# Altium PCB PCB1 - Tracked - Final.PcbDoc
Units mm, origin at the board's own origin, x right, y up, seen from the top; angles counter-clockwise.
Board outline 152.4 x 101.6 mm, 4 copper layers (Top Layer, Internal Plane 1, Internal Plane 2, Bottom Layer), stack 0.462 mm thick; 14 components, 52 nets, 174 pads, 10 vias.
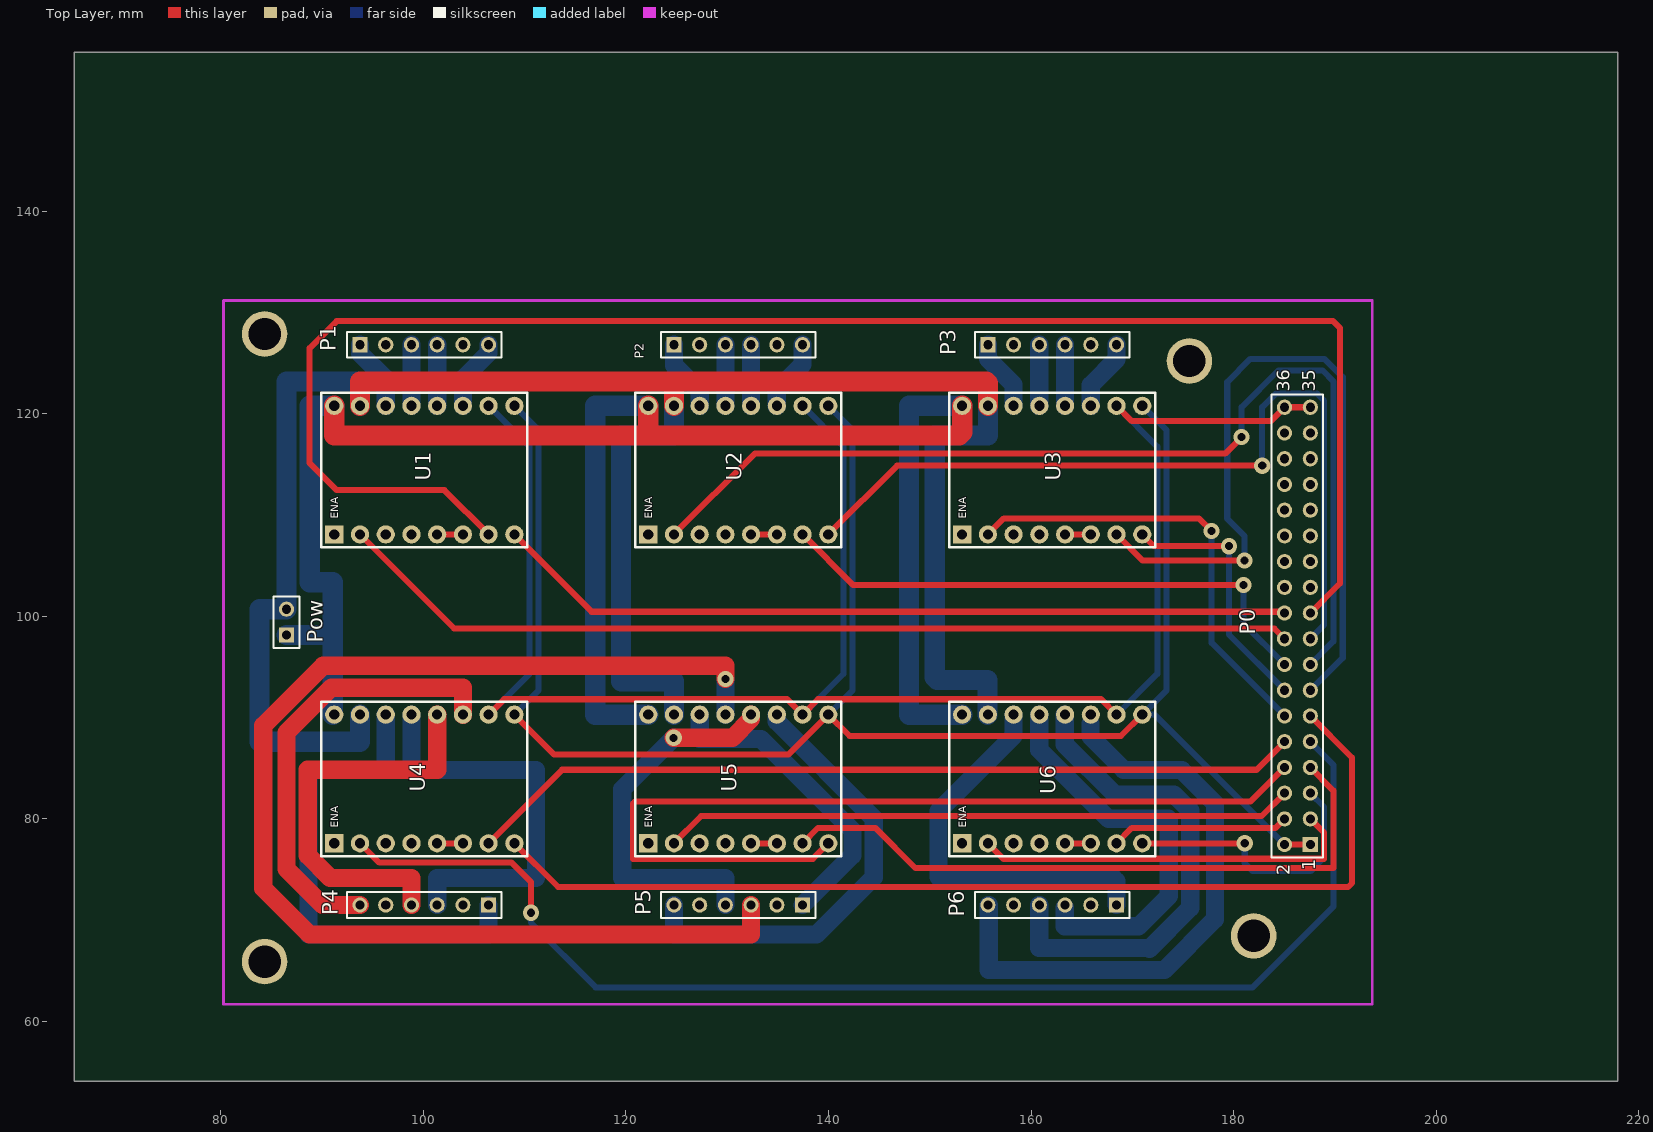
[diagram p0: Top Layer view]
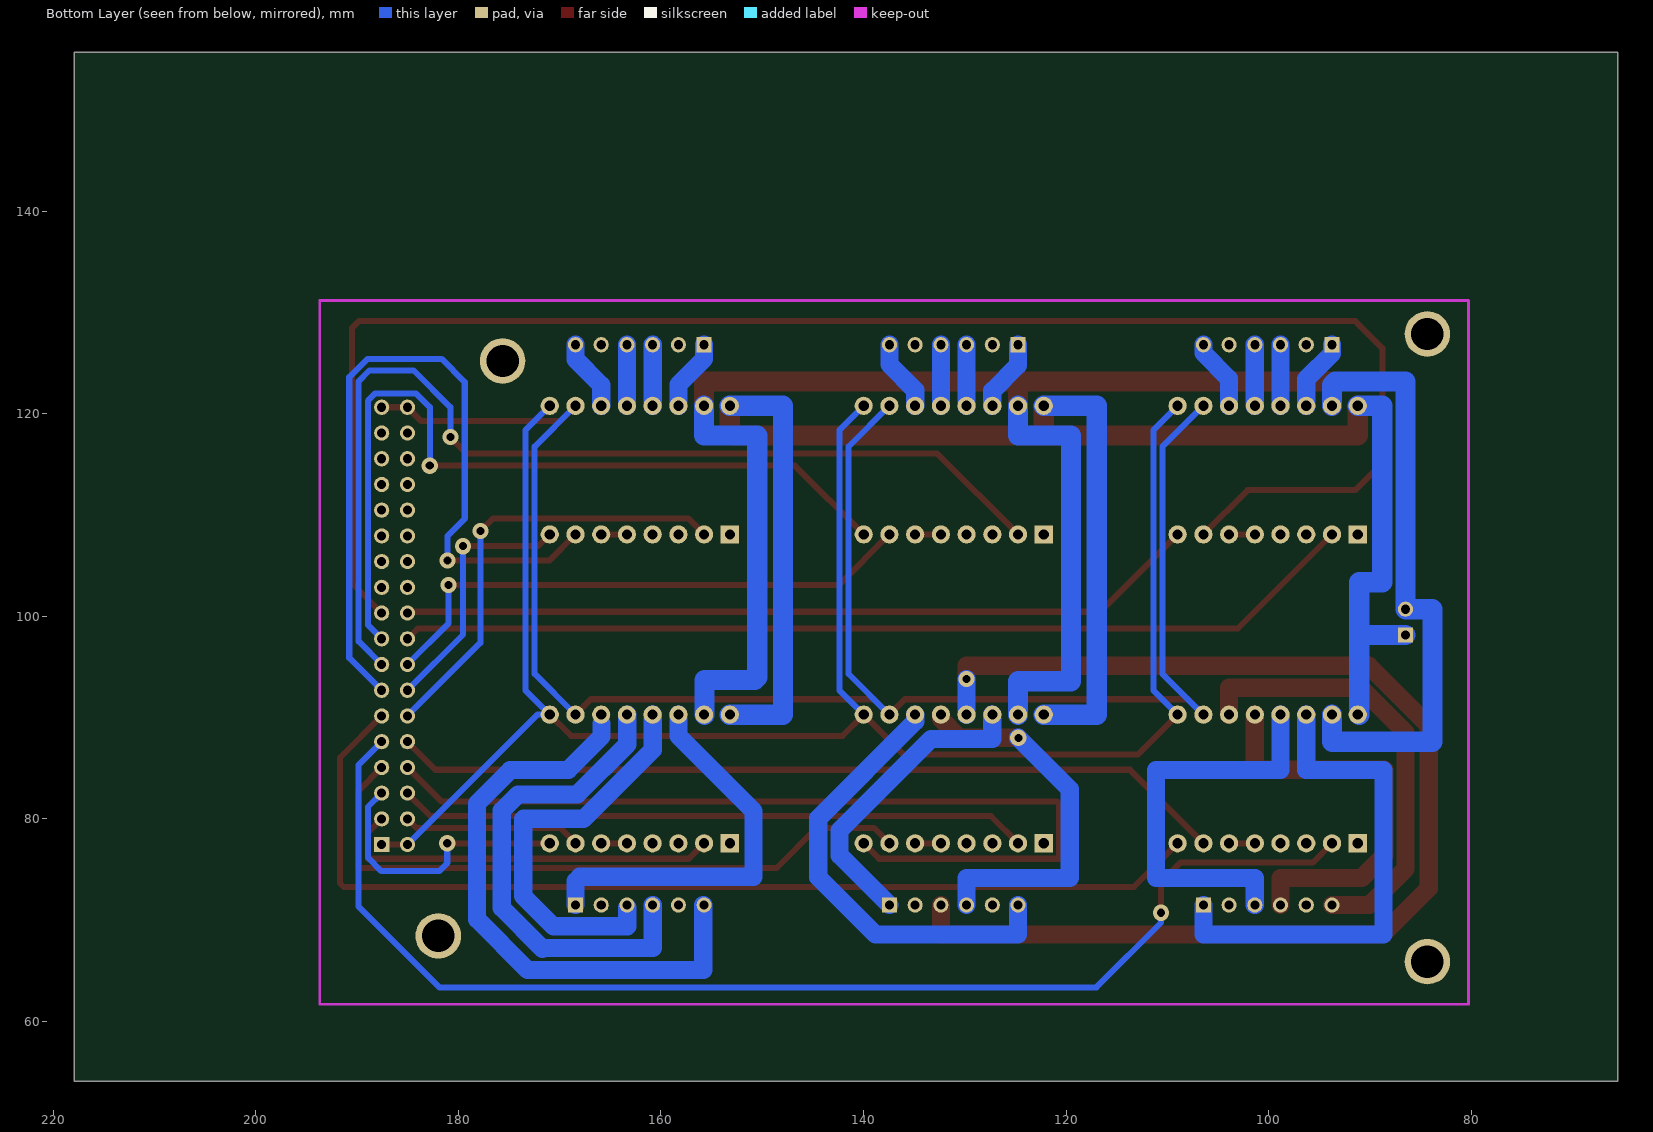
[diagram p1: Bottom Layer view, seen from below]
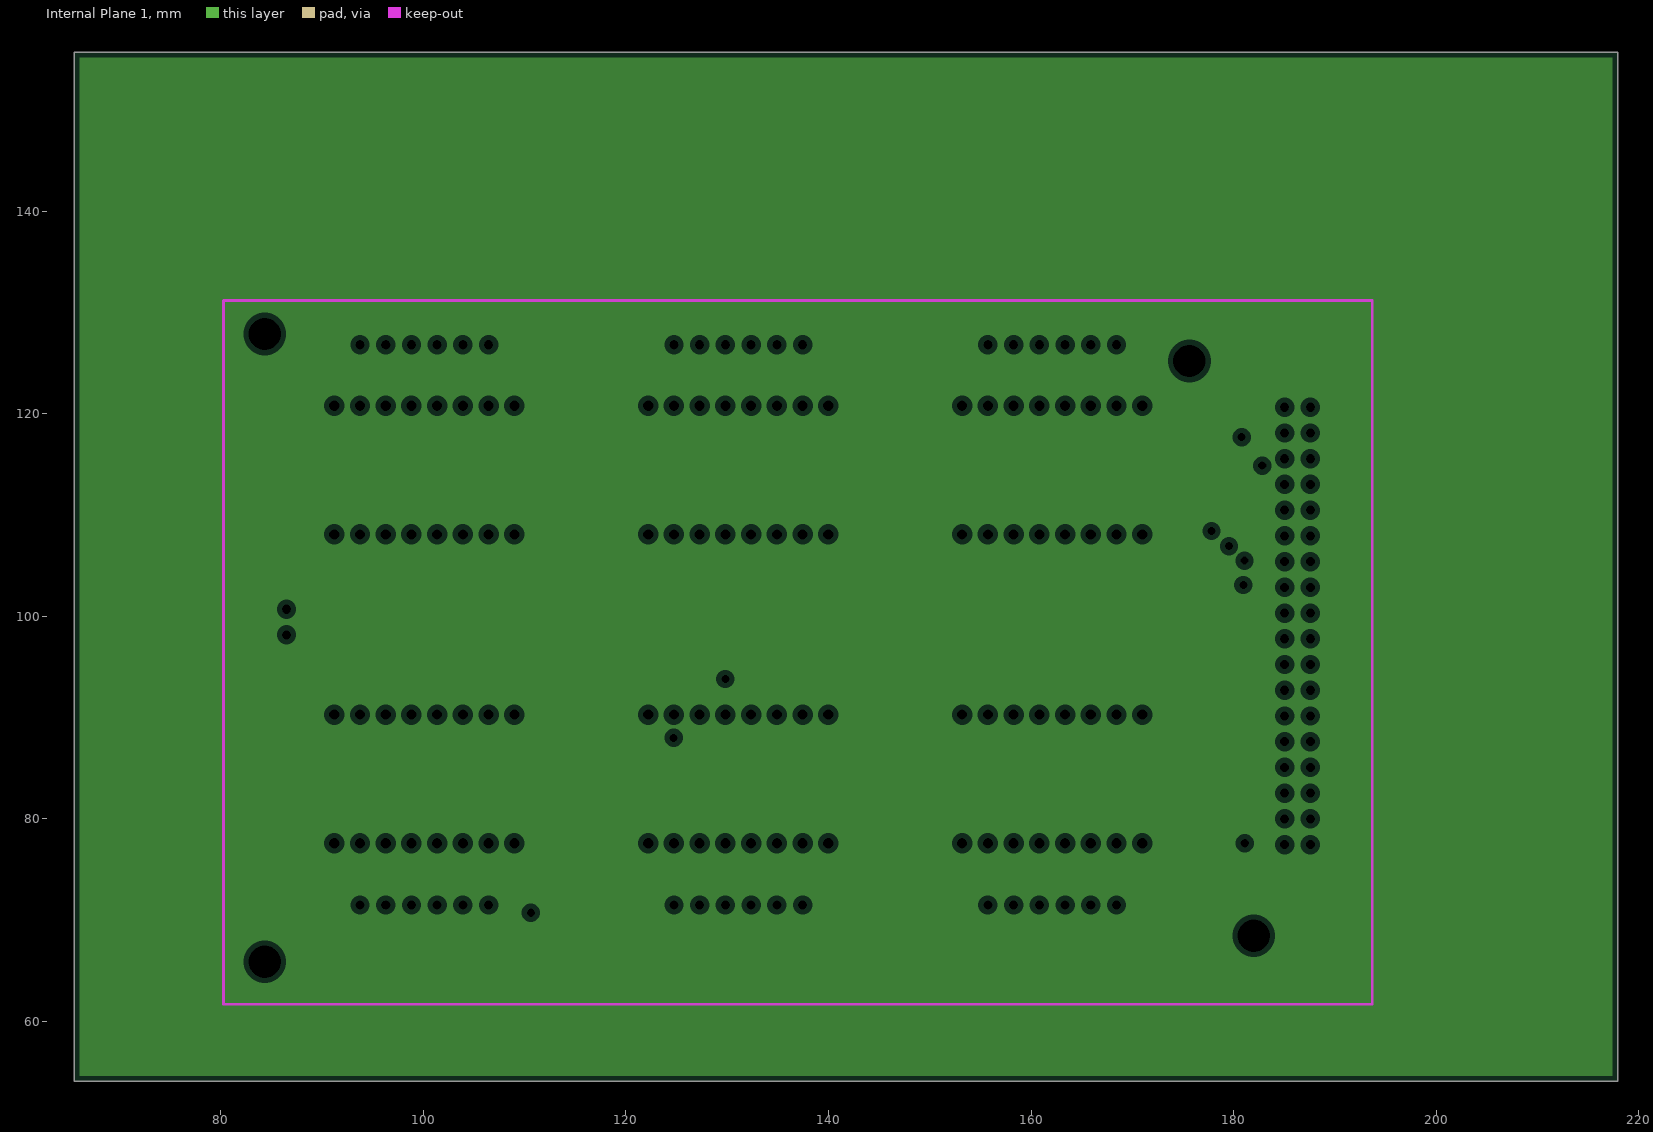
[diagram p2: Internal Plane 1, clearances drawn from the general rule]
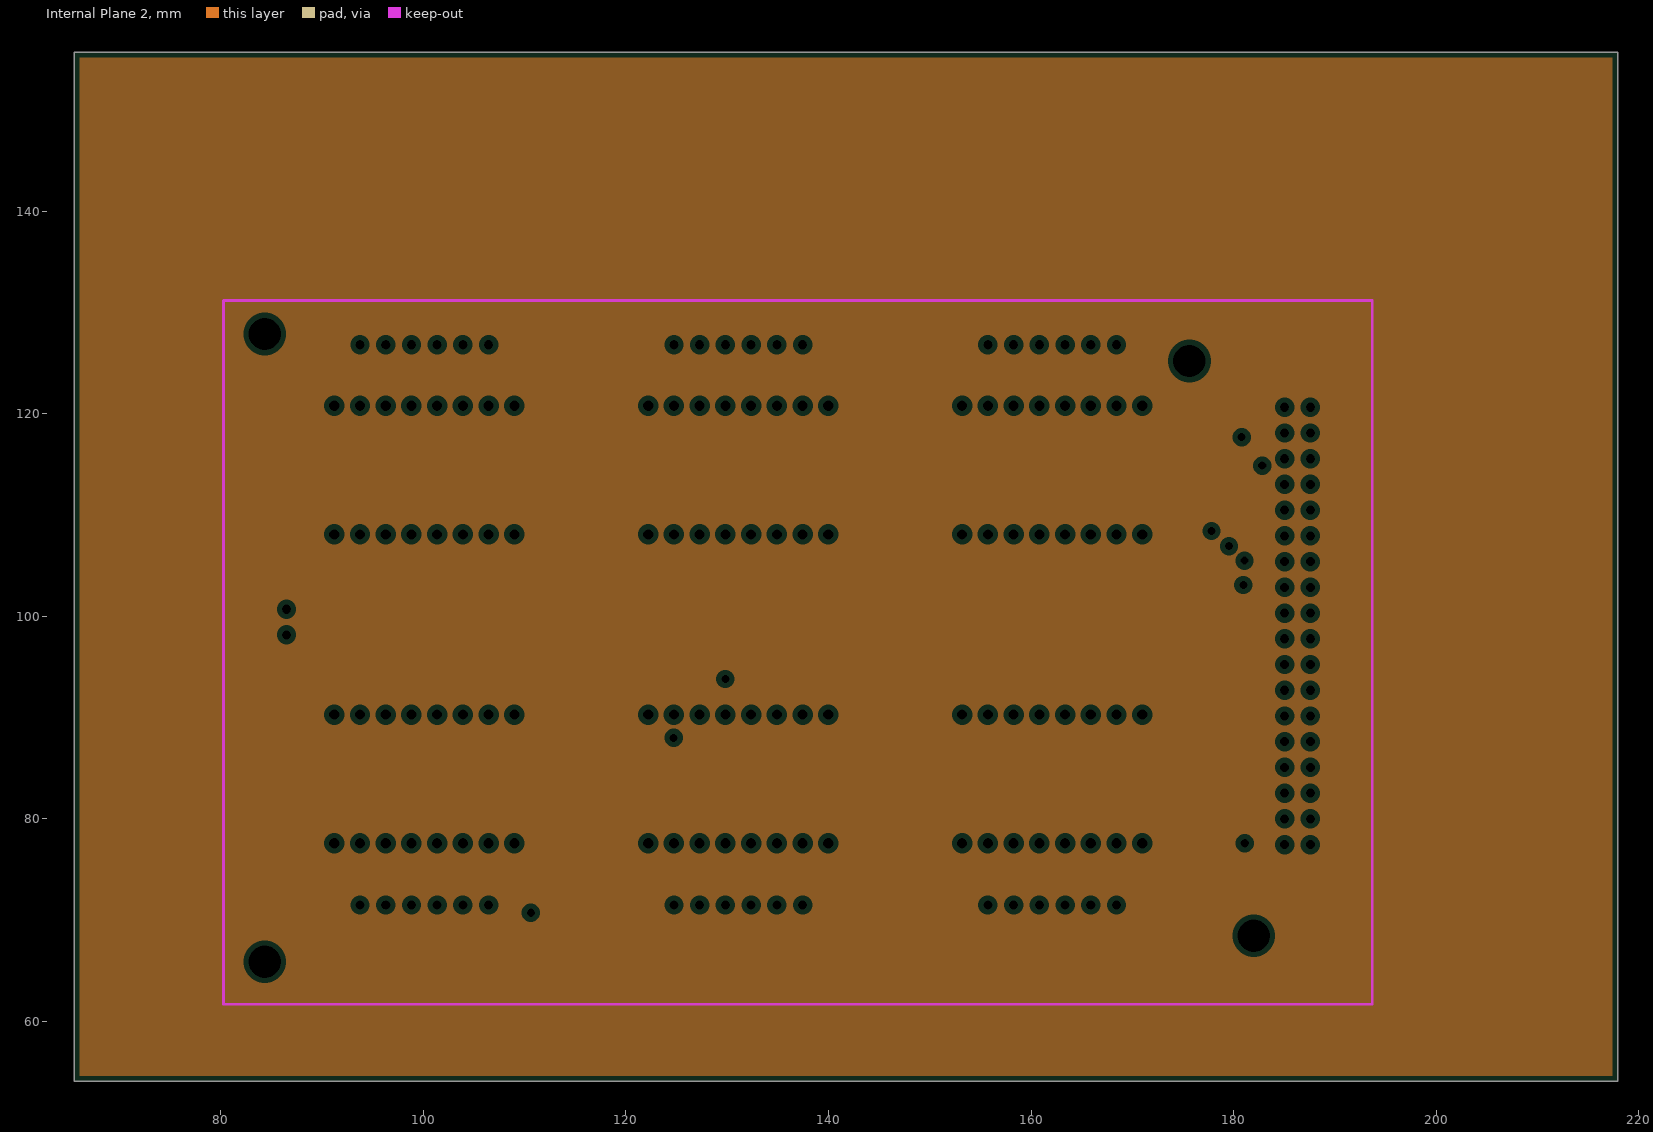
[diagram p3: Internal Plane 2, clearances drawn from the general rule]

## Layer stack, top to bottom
Top Solder: solder mask 0.0102, Solder Resist, Dk 3.5
Top Layer: signal copper 0.0356
Internal Plane 1: plane copper 0.0356
Internal Plane 2: plane copper 0.0356
Dielectric1: dielectric 0.32, FR-4, Dk 4.8
Bottom Layer: signal copper 0.0356
Bottom Solder: solder mask 0.0102, Solder Resist, Dk 3.5

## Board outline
65.532,54.102 65.532,155.702 217.932,155.702 217.932,54.102

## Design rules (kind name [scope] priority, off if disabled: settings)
AssemblyTestPointUsage AssemblyTestPointUsage_1 [All] p2:
AssemblyTestpoint AssemblyTestpoint_1 [All] p2: testpointundercomponent=TRUE minsize=1.016 maxsize=2.54 preferedsize=1.524 minholesize=0 maxholesize=1.016 preferedholesize=0.813 testpointgrid=0.025 usegrid=TRUE gridtolerance=0 allowsidetop=TRUE allowsidebottom=TRUE
Clearance [All] p1: gap=0.3
ComponentClearance ComponentClearance_1 [All] p2: gap=0.254 collisioncheckmode=3 verticalgap=0.254 showdistances=FALSE
DiffPairsRouting DiffPairsRouting_1 [All] p2: maxlimit=0.254 minlimit=0.254 mostfreqgap=0.254 toplayer_minwidth=0.381 toplayer_maxwidth=0.381 toplayer_prefwidth=0.381 bottomlayer_minwidth=0.381 bottomlayer_maxwidth=0.381 bottomlayer_prefwidth=0.381 maxuncoupledlength=12.7
FabricationTestPointUsage TestPointUsage [All] p2: valid=0 allowmultiple=FALSE
FabricationTestpoint Testpoint [All] p2: side=3 testpointundercomponent=TRUE minsize=1.016 maxsize=2.54 preferedsize=1.524 minholesize=0 maxholesize=1.016 preferedholesize=0.813 testpointgrid=0.025 allowsidetop=TRUE allowsidebottom=TRUE usegrid=TRUE gridtolerance=0
FanoutControl Fanout_LCC [IsLCC] p1: bgadir=Out bgaviamode=Centered fanoutstyle=Auto fanoutdirection=Alternating viagrid=0.025 // Fanout_LCC (Default Rule)
FanoutControl Fanout_BGA [IsBGA] p2: bgadir=Out bgaviamode=Centered fanoutstyle=Auto fanoutdirection=Alternating viagrid=0.025 // Fanout_BGA (Default Rule)
FanoutControl Fanout_Default [All] p4: bgadir=Out bgaviamode=Centered fanoutstyle=Auto fanoutdirection=Alternating viagrid=0.025 // Fanout_Default (Default Rule)
FanoutControl Fanout_Small [(CompPinCount < 5)] p5: bgadir=Out bgaviamode=Centered fanoutstyle=Auto fanoutdirection=OutThenIn viagrid=0.025 // Fanout_Small (Default Rule)
FanoutControl Fanout_BGA_1 [IsBGA] p6: bgadir=Out bgaviamode=Centered fanoutstyle=Auto fanoutdirection=Alternating viagrid=0.025 // Fanout_BGA (Default Rule)
FanoutControl Fanout_LCC_1 [IsLCC] p7: bgadir=Out bgaviamode=Centered fanoutstyle=Auto fanoutdirection=Alternating viagrid=0.025 // Fanout_LCC (Default Rule)
FanoutControl Fanout_SOIC_1 [IsSOIC] p8: bgadir=Out bgaviamode=Centered fanoutstyle=Auto fanoutdirection=Alternating viagrid=0.025 // Fanout_SOIC (Default Rule)
FanoutControl Fanout_Small_1 [(CompPinCount < 5)] p9: bgadir=Out bgaviamode=Centered fanoutstyle=Auto fanoutdirection=OutThenIn viagrid=0.025 // Fanout_Small (Default Rule)
FanoutControl Fanout_Default_1 [All] p10: bgadir=Out bgaviamode=Centered fanoutstyle=Auto fanoutdirection=Alternating viagrid=0.025 // Fanout_Default (Default Rule)
Height Height_1 [All] p2: minheight=0 maxheight=25.4 prefheight=12.7
HoleSize HoleSize_1 [All] p2: absolutevalues=TRUE maxlimit=2.54 minlimit=0.025 maxpercent=80.000 minpercent=20.000
HoleToHoleClearance HoleToHoleClearance_1 [All] p2: gap=0.254 allowstackedmicrovias=TRUE
LayerPairs LayerPairs_1 [All] p2: enforce=TRUE
MinimumSolderMaskSliver MinimumSolderMaskSliver_1 [All] p2: minsoldermaskwidth=0.254
NetAntennae NetAntennae_1 [All] p2: netantennaetolerance=0
PasteMaskExpansion PasteMaskExpansion_1 [All] p2: expansion=0
PlaneClearance [All] p1: clearance=0.508
PlaneClearance PlaneClearance_1 [All] p2: clearance=0.508
PlaneConnect [All] p1: planeconnectstyle=Relief reliefexpansion=0.508 reliefentries=4 reliefconductorwidth=0.254 reliefairgap=0.254
PolygonConnect [All] p1: connectstyle=Relief reliefconductorwidth=0.254 reliefentries=4 polygonreliefangle="90 Angle" airgapwidth=0.254
PolygonConnect PolygonConnect_1 [All] p2: connectstyle=Relief reliefconductorwidth=0.254 reliefentries=4 polygonreliefangle="90 Angle" airgapwidth=0.254
RoutingPriority RoutingPriority_1 [All] p2: routingpriority=0
RoutingTopology RoutingTopology_1 [All] p2: topology=Shortest
RoutingVias [All] p1: holewidth=0.8 width=1.6 viastyle="Through Hole" minholewidth=0.711 minwidth=1.27 maxholewidth=0.711 maxwidth=1.27
ShortCircuit ShortCircuit_1 [All] p2: allowed=FALSE
SilkToBoardRegionClearance SilkToBoardRegionClearance_1 [All] p2:
SilkToSilkClearance SilkToSilkClearance_1 [All] p2: silktosilkclearance=0.254
SilkToSolderMaskClearance SilkscreenOverComponentPads [IsPad] p2: minsilkscreentomaskgap=0.254 clearancetoexposedcopper=TRUE
SolderMaskExpansion [All] p1: expansion=0.102
SolderMaskExpansion SolderMaskExpansion_1 [All] p2: expansion=0.102
UnRoutedNet UnRoutedNet_1 [All] p2:
UnpouredPolygon UnpouredPolygon_1 [All] p2:
Width [All] p1: maxlimit=1.8 minlimit=0.6 preferedwidth=0.6
24 further rules are at their usual default settings.

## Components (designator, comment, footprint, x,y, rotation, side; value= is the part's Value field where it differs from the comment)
P0 "Header 18X2" HDR2X18 187.579,77.47 r90 top
P1 "Header 6" HDR1X6#1 93.744,126.825 r0 top
P2 "Header 6" HDR1X6#1 124.744,126.825 r0 top
P3 "Header 6" HDR1X6#1 155.744,126.825 r0 top
P4 "Header 6" HDR1X6#2 93.744,71.501 r0 top
P5 "Header 6" HDR1X6#2 124.744,71.501 r0 top
P6 "Header 6" HDR1X6#2 155.744,71.501 r0 top
Pow "Header 2" HDR1X2 86.487,98.171 r90 top
U1 "Stepper motor driver" PCBDriver_1 110,106.825 r90 top
U2 "Stepper motor driver" PCBDriver_1 141,106.825 r90 top
U3 "Stepper motor driver" PCBDriver_1 172,106.825 r90 top
U4 "Stepper motor driver" PCBDriver_1 110,76.327 r90 top
U5 "Stepper motor driver" PCBDriver_1 141,76.327 r90 top
U6 "Stepper motor driver" PCBDriver_1 172,76.327 r90 top

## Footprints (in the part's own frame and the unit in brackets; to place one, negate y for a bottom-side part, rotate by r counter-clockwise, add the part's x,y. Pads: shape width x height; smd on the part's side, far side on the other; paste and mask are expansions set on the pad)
HDR1X2 [mm] "Connector; Header; 2 Position"
  rect 1.5x1.5 hole 0.9: 1(0,0)
  round 1.5 hole 0.9: 2(2.54,0)
  silkscreen extent -1.27,-1.27 3.81,1.27
HDR1X6#1 [mm] "Connector; Header; 6 Position"
  rect 1.5x1.5 hole 0.9: 1(0,0)
  round 1.5 hole 0.9: 2(2.54,0) 3(5.08,0) 4(7.62,0) 5(10.16,0) 6(12.7,0)
  silkscreen extent -1.27,-1.27 13.97,1.27
HDR1X6#2 [mm] "Connector; Header; 6 Position"
  round 1.5 hole 0.9: 1(0,0) 2(2.54,0) 3(5.08,0) 4(7.62,0) 5(10.16,0)
  rect 1.5x1.5 hole 0.9: 6(12.7,0)
  silkscreen extent -1.27,-1.27 13.97,1.27
HDR2X18 [mm] "Connector; Header; 18x2 Position"
  rect 1.5x1.5 hole 0.9: 1(0,0)
  round 1.5 hole 0.9: 2(0,2.54) 3(2.54,0) 4(2.54,2.54) 5(5.08,0) 6(5.08,2.54) 7(7.62,0) 8(7.62,2.54) 9(10.16,0) 10(10.16,2.54) 11(12.7,0) 12(12.7,2.54) 13(15.24,0) 14(15.24,2.54) 15(17.78,0) 16(17.78,2.54) 17(20.32,0) 18(20.32,2.54) 19(22.86,0) 20(22.86,2.54) 21(25.4,0) 22(25.4,2.54) 23(27.94,0) 24(27.94,2.54) 25(30.48,0) 26(30.48,2.54) 27(33.02,0) 28(33.02,2.54) 29(35.56,0) 30(35.56,2.54) 31(38.1,0) 32(38.1,2.54) 33(40.64,0) 34(40.64,2.54) 35(43.18,0) 36(43.18,2.54)
  silkscreen extent -1.27,-1.27 44.45,3.81
PCBDriver_1 [mm] "Stepper motor driver A4988"
  rect 1.8x1.8 hole 1: 0(1.27,18.796)
  round 1.8 hole 1: 1(1.27,16.256) 2(1.27,13.716) 3(1.27,11.176) 4(1.27,8.636) 5(1.27,6.096) 6(1.27,3.556) 7(1.27,1.016) 8(13.97,1.016) 9(13.97,3.556) 10(13.97,6.096) 11(13.97,8.636) 12(13.97,11.176) 13(13.97,13.716) 14(13.97,16.256) 15(13.97,18.796)
  silkscreen extent 0,-0.25 15.24,20.07

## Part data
P0: "Header, 18-Pin, Dual row"
P1 P2 P3 P4 P5 P6: "Header, 6-Pin"
Pow: "Header, 2-Pin"
U1 U2 U3 U4 U5 U6: library part Driver_1, "Stepper Motor Driver module A4988"

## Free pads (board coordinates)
  round 4.5 hole 3.2: 0(84.328,65.913) 0(84.328,127.889) 0(175.641,125.222) 0(181.991,68.453)

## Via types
v1: diameter 1.6, hole 0.8, Top Layer to Bottom Layer, 10 vias

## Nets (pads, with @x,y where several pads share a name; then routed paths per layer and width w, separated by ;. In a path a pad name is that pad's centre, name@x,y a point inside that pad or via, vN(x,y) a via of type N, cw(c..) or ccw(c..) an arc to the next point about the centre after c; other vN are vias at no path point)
NetP0_1: P0.1 P0.2 U1.8 U2.8 U3.8 U4.8 U5.8 U6.8 | length 186.4
  Top Layer w0.6: U4.8 112.921,86.36 136.047,86.36 U5.8 142.092,88.189 168.876,88.189 U6.8 ; P0.2 P0.1
  Bottom Layer w0.6: U4.8 111.384,92.697 111.384,118.395 U1.8 ; U5.8 142.384,92.697 142.384,118.395 U2.8 ; U3.8 173.384,118.395 173.384,92.697 U6.8 172.212,90.297 P0.2
NetP0_3: P0.3 U6.1 | length 38.3
  Top Layer w0.6: U6.1 157.268,76.073 188.951,76.073 188.951,78.638 P0.3
NetP0_4: P0.4 U6.6 | length 17.6
  Top Layer w0.6: U6.6 169.968,79.121 184.15,79.121 P0.4
NetP0_5: P0.5 U6.7 | length 27.7
  Top Layer w0.6: U6.7 v1(181.102,77.597)
  Bottom Layer w0.6: v1(181.102,77.597) 181.102,75.641 181.889,74.854 187.604,74.854 188.951,76.2 188.951,81.178 P0.5
NetP0_6: P0.6 U5.1 | length 62.3
  Top Layer w0.6: U5.1 127.436,80.289 182.778,80.289 P0.6
NetP0_7: P0.7 U5.6 | length 65.6
  Top Layer w0.6: U5.6 138.968,79.121 144.628,79.121 148.59,75.159 189.865,75.159 189.865,82.804 P0.7
NetP0_8: P0.8 U5.7 | length 91.2
  Top Layer w0.6: U5.7 138.46,76.073 120.701,76.073 120.701,81.509 120.929,81.737 181.686,81.737 P0.8
NetP0_9: P0.9 U4.1 | length 124.9
  Top Layer w0.6: U4.1 95.649,75.692 108.712,75.692 110.617,73.787 v1(110.617,70.739)
  Bottom Layer w0.6: v1(110.617,70.739) 110.617,69.774 117.018,63.373 181.889,63.373 189.865,71.349 189.865,85.344 P0.9
NetP0_10: P0.10 U4.6 | length 82.8
  Top Layer w0.6: U4.6 113.708,84.861 182.27,84.861 P0.10
NetP0_11: P0.11 U4.7 | length 102.9
  Top Layer w0.6: U4.7 113.302,73.279 191.313,73.279 191.694,73.66 191.694,86.055 P0.11
NetP0_12: P0.12 U3.1 | length 44.5
  Top Layer w0.6: U3.1 157.326,109.677 176.581,109.677 v1(177.825,108.433)
  Bottom Layer w0.6: v1(177.825,108.433) 177.825,97.384 P0.12
NetP0_13: P0.13 U3.6 | length 77.4
  Top Layer w0.6: U3.6 171.027,105.512 v1(181.077,105.512)
  Bottom Layer w0.6: v1(181.077,105.512) 181.077,107.95 179.375,109.652 179.375,123.141 181.659,125.425 188.976,125.425 190.779,123.622 190.779,95.91 P0.13
NetP0_14: P0.14 U3.7 | length 25.5
  Top Layer w0.6: U3.7 172.145,106.934 v1(179.553,106.934)
  Bottom Layer w0.6: v1(179.553,106.934) 179.553,98.196 P0.14
NetP0_15: P0.15 U2.1 | length 102.9
  Top Layer w0.6: U2.1 132.727,116.078 179.172,116.078 v1(180.797,117.704)
  Bottom Layer w0.6: v1(180.797,117.704) 180.797,120.65 184.429,124.282 188.798,124.282 189.865,123.215 189.865,97.536 P0.15
NetP0_16: P0.16 U2.6 | length 55.1
  Top Layer w0.6: U2.6 142.44,103.099 v1(180.975,103.099)
  Bottom Layer w0.6: v1(180.975,103.099) 180.975,99.314 P0.16
NetP0_17: P0.17 U2.7 | length 82.5
  Top Layer w0.6: U2.7 146.773,114.884 v1(182.829,114.884)
  Bottom Layer w0.6: v1(182.829,114.884) 182.829,120.65 184.201,122.022 188.214,122.022 188.951,121.285 188.951,99.162 P0.17
NetP0_18: P0.18 U1.1 | length 95.6
  Top Layer w0.6: U1.1 103.033,98.806 184.023,98.806 P0.18
NetP0_19: P0.19 U1.6 | length 164.4
  Top Layer w0.6: U1.6 102.068,112.471 91.44,112.471 88.773,115.138 88.773,126.492 91.44,129.159 189.84,129.159 190.5,128.499 190.5,103.251 P0.19
NetP0_20: P0.20 U1.7 | length 79.3
  Top Layer w0.6: U1.7 116.622,100.457 185.039,100.457 P0.20
NetP0_35: P0.35 P0.36 U1.9 U2.9 U3.9 U4.9 U5.9 U6.9 | length 186.4
  Top Layer w0.6: U4.9 107.968,91.821 135.92,91.821 U5.9 138.968,91.821 166.92,91.821 U6.9 ; U3.9 169.961,119.278 183.667,119.278 P0.36 P0.35
  Bottom Layer w0.6: U4.9 110.484,94.337 110.484,116.755 U1.9 ; U5.9 141.484,94.337 141.484,116.755 U2.9 ; U6.9 172.484,94.337 172.484,116.755 U3.9
NetP1_1: P1.1 U1.13 | length 7.1
  Bottom Layer w1.8: P1.1 93.744,125.966 96.284,123.426 U1.13
NetP1_3: P1.3 U1.12 | length 6
  Bottom Layer w1.8: U1.12 P1.3
NetP1_4: P1.4 U1.11 | length 6
  Bottom Layer w1.8: U1.11 P1.4
NetP1_6: P1.6 U1.10 | length 7.1
  Bottom Layer w1.8: U1.10 103.904,123.462 106.444,126.002 P1.6
NetP2_1: P2.1 U2.13 | length 7.1
  Bottom Layer w1.8: P2.1 124.744,124.811 127.284,122.271 U2.13
NetP2_3: P2.3 U2.12 | length 6
  Bottom Layer w1.8: U2.12 P2.3
NetP2_4: P2.4 U2.11 | length 6
  Bottom Layer w1.8: U2.11 P2.4
NetP2_6: P2.6 U2.10 | length 7.1
  Bottom Layer w1.8: U2.10 134.904,122.331 137.444,124.871 P2.6
NetP3_1: P3.1 U3.13 | length 7.1
  Bottom Layer w1.8: P3.1 155.744,125.434 158.284,122.894 U3.13
NetP3_3: P3.3 U3.12 | length 6
  Bottom Layer w1.8: U3.12 P3.3
NetP3_4: P3.4 U3.11 | length 6
  Bottom Layer w1.8: U3.11 P3.4
NetP3_6: P3.6 U3.10 | length 7.1
  Bottom Layer w1.8: U3.10 165.904,122.851 168.444,125.391 P3.6
NetP4_1: P4.1 U4.10 | length 43.9
  Top Layer w1.8: 90.774,92.837 86.487,88.55 86.487,75.057 90.043,71.501 P4.1 ; 90.932,92.964 103.904,92.964 U4.10
NetP4_3: P4.3 U4.11 | length 40.5
  Top Layer w1.8: P4.3 98.824,74.168 90.805,74.168 88.587,76.386 88.587,84.854 101.364,84.854 U4.11
NetP4_4: P4.4 U4.12 | length 40.9
  Bottom Layer w1.8: U4.12 98.824,84.836 111.125,84.836 111.125,74.168 101.364,74.168 P4.4
NetP4_6: P4.6 U4.13 | length 50.1
  Bottom Layer w1.8: U4.13 96.284,84.836 88.646,84.836 88.646,68.58 106.444,68.58 P4.6
NetP5_1: P5.1 U5.10 | length 45
  Bottom Layer w1.8: P5.1 124.744,68.58 138.811,68.58 144.467,74.236 144.467,80.069 134.904,89.632 U5.10
NetP5_3: P5.3 U5.11 | length 37.7
  Top Layer w1.8: v1(124.714,88.011) 130.508,88.011 132.364,89.867 U5.11
  Bottom Layer w1.8: v1(124.714,88.011) 119.634,82.931 119.634,74.168 129.824,74.168 P5.3
NetP5_4: P5.4 U5.12 | length 121.5
  Top Layer w1.8: 129.413,95.123 90.09,95.123 84.201,89.234 84.201,73.152 88.773,68.58 132.364,68.58 P5.4 ; v1(129.824,93.823) 129.824,95.123
  Bottom Layer w1.8: U5.12 v1(129.824,93.823)
NetP5_6: P5.6 U5.13 | length 30.6
  Bottom Layer w1.8: U5.13 127.284,87.884 133.35,87.884 139.776,81.458 142.367,78.867 142.367,76.424 P5.6
NetP6_1: P6.1 U6.10 | length 59.1
  Bottom Layer w0.6: U6.10@165.439,89.831 U6.10@165.862,89.408
  Bottom Layer w1.8: 155.829,65.083 173.16,65.083 178.181,70.104 178.181,81.534 174.879,84.836 169.164,84.836 165.862,88.138 U6.10@165.862,89.408 ; 155.829,65.151 P6.1@155.829,71.501
NetP6_3: P6.3 U6.11 | length 48.5
  Bottom Layer w1.8: P6.3 160.824,67.251 171.704,67.251 ; U6.11@163.322,90.297 163.322,87.376 168.275,82.423 174.117,82.423 175.717,80.823 175.717,71.196 171.704,67.183
NetP6_4: P6.4 U6.12 | length 40
  Bottom Layer w1.8: U6.12 160.824,86.826 167.64,80.01 173.56,80.01 173.609,79.961 173.609,72.39 170.62,69.401 163.322,69.401 P6.4@163.322,71.247
NetP6_6: P6.6 U6.13 | length 39.2
  Bottom Layer w0.6: 168.021,74.295 168.444,73.872
  Bottom Layer w1.8: U6.13 158.284,88.18 150.876,80.772 150.876,74.295 168.021,74.295 ; P6.6 168.444,73.872
NetPow_1: Pow.1 U1.15 U2.15 U3.15 U4.15 U5.15 U6.15 | length 192.4
  Top Layer w0.6: 152.908,117.856 153.204,118.152
  Top Layer w2: U1.15 91.204,117.856 122.204,117.856 ; U2.15 122.204,117.856 ; 152.908,117.856 122.204,117.856 ; 153.204,118.152 U3.15
  Bottom Layer w2: Pow.1 91.059,98.171 ; U4.15@91.059,90.297 91.059,103.378 88.787,103.378 88.787,120.795 U1.15 ; U5.15 116.967,90.297 116.967,120.795 U2.15 ; U6.15 147.955,90.297 147.955,120.795 U3.15
NetPow_2: Pow.2 U1.14 U2.14 U3.14 U4.14 U5.14 U6.14 | length 213.4
  Top Layer w0.6: U2.14 124.744,123.347 124.901,123.19 ; 155.575,123.19 155.744,123.021
  Top Layer w2: U1.14 93.744,123.19 124.333,123.19 ; U2.14 124.744,123.19 155.575,123.19 ; U3.14 155.744,123.021
  Bottom Layer w2: U4.14 93.744,87.63 83.82,87.63 83.82,100.711 Pow.2 86.487,123.19 93.409,123.19 93.744,122.855 U1.14 ; U5.14 124.744,93.472 ; 124.744,93.599 119.507,93.599 119.507,117.856 124.744,117.856 U2.14 ; U6.14@155.702,90.297 155.702,93.726 150.749,93.726 150.495,93.98 150.495,117.856 155.744,117.856 U3.14
NetU1_4: U1.4 U1.5 | length 2.5
  Top Layer w0.6: U1.4 U1.5
NetU2_4: U2.4 U2.5 | length 2.5
  Top Layer w0.6: U2.4 U2.5
NetU3_4: U3.4 U3.5 | length 2.5
  Top Layer w0.6: U3.4 U3.5
NetU4_4: U4.4 U4.5 | length 2.5
  Top Layer w0.6: U4.4 U4.5
NetU5_4: U5.4 U5.5 | length 2.5
  Top Layer w0.6: U5.4 U5.5
NetU6_4: U6.4 U6.5 | length 2.5
  Top Layer w0.6: U6.4 U6.5
pads on no net: P0.21 P0.22 P0.23 P0.24 P0.25 P0.26 P0.27 P0.28 P0.29 P0.30 P0.31 P0.32 P0.33 P0.34 P1.2 P1.5 P2.2 P2.5 P3.2 P3.5 P4.2 P4.5 P5.2 P5.5 P6.2 P6.5 U1.0 U1.2 U1.3 U2.0 U2.2 U2.3 U3.0 U3.2 U3.3 U4.0 U4.2 U4.3 U5.0 U5.2 U5.3 U6.0 U6.2 U6.3

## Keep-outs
Keep-Out Layer:
  lines w0.254: 80.264,61.722 193.675,61.722 193.675,131.191 80.264,131.191 80.264,61.722

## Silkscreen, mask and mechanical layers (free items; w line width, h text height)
Mechanical 16:
  drawing of 1873 lines, arcs and shapes, not listed
  text "1" at 36.246,189.611 h1.78
  text "2" at 108.89,189.611 h1.78
  text "3" at 182.042,189.611 h1.78
  text "4" at 254.94,189.611 h1.78
  text "A" at 1.905,166.599 h1.78
  text "A" at 288.925,166.599 h1.78
  text "B" at 1.905,118.542 h1.78
  text "B" at 288.925,118.542 h1.78
  text "C" at 1.905,70.028 h1.78
  text "ENGINEER:" at 173.99,33.02 h1.14
  text "TITLE:" at 212.09,33.02 h1.14
  text "PCB DESIGNER:" at 173.99,25.527 h1.14
  text "D" at 1.905,22.022 h1.78
  text "D" at 288.925,22.022 h1.78
  text "DATE:" at 173.99,17.78 h1.14
  text "PART NO.:" at 212.09,17.78 h1.14
  text "REV:" at 265.43,17.78 h1.14
  text "Altium Limited" at 140.97,15.24 h1.78
  text ".PRINT_DATE" at 175.26,14.732 h1.78
  text "12a Rodborough Rd" at 140.97,12.7 h1.78
  text "Frenchs Forest" at 140.97,10.16 h1.78
  text "FILE NAME:" at 173.99,10.16 h1.14
  text "DWG NO:" at 212.09,10.16 h1.14
  text "SCALE:" at 265.43,10.16 h1.14
  text "NSW 2086" at 140.97,7.62 h1.78
  text ".PCB_FILE_NAME_NO_PATH" at 175.26,7.112 h1.78
  text "1" at 36.246,1.651 h1.78
  text "2" at 108.89,1.651 h1.78
  text "3" at 182.042,1.651 h1.78
  text "4" at 254.94,1.651 h1.78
